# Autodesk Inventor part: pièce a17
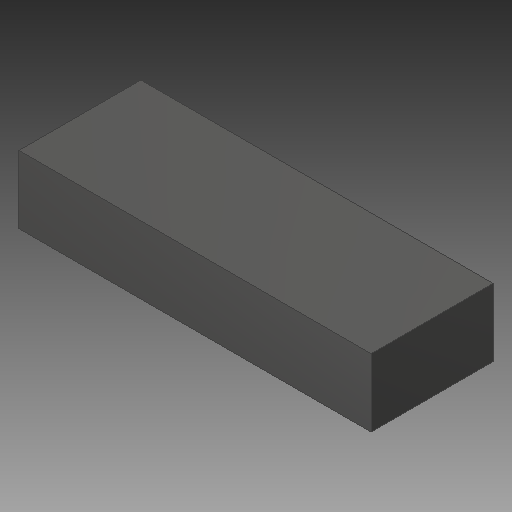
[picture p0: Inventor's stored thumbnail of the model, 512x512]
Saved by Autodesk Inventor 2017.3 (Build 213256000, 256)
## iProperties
Created: 2007-12
Part Number: pièce a17
Material: solidworks materials|PVC 0.007 plastifié|45
Document SubType Name: Modeling
Designer: ficho
Appearance: 0,0,0
Author: ficho
Sending System: SolidWorks 2009
Last Author: christophe
Last Saved: 2011-02-10
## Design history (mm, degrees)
extrude "Extrusion1"
node "Solide1"
